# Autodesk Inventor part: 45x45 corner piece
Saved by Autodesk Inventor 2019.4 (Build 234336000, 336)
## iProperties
Created: 2020-04
Part Number: 45x45 corner piece
Material: Generic
Document SubType Name: Modeling
Designer: Administrator
Density: 1 g/cm^3
Appearance: Default
Title: 45x45 corner piece v3
Author: Administrator
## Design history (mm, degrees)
feature "Body1"
body "Solid1"
